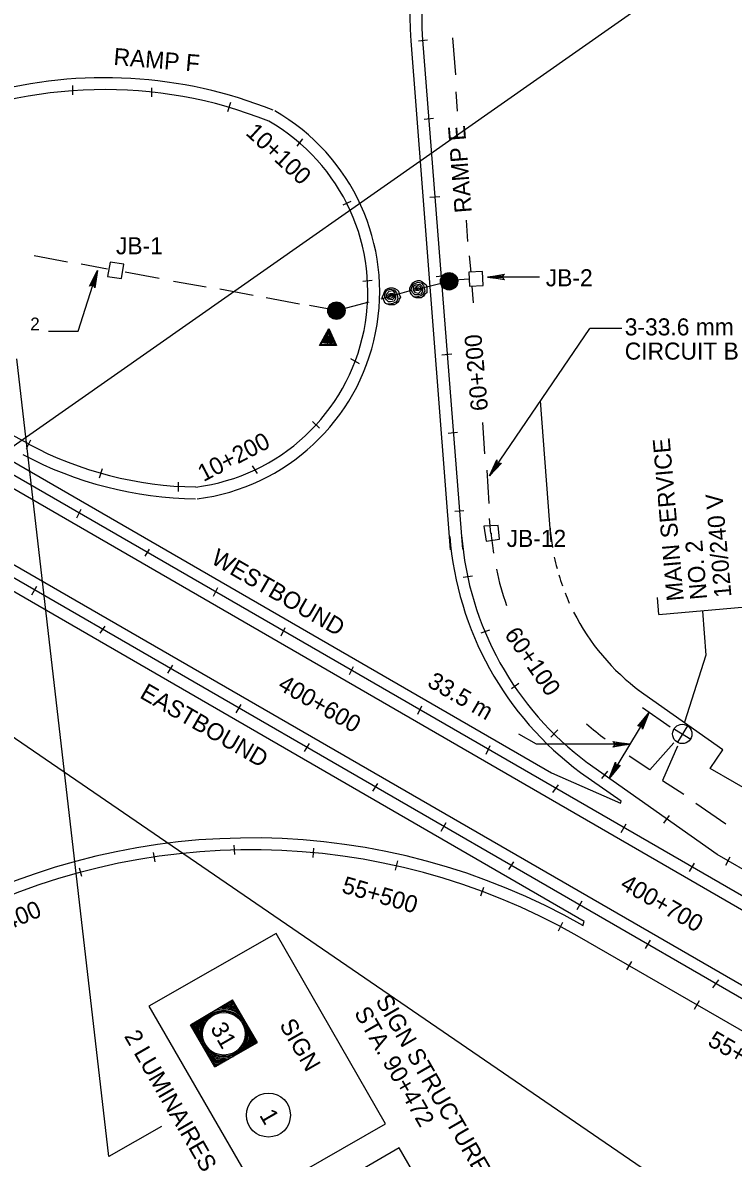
# Model space of a CAD drawing. Extents: x 36 to 2622, y -5330 to 219.
# Drawn here: x 2175.5 to 2300.3, y -4537.5 to -4338.2 of the extents above; entities that cross this region are included whole.
import ezdxf

# ---------------------------------------------------------------- set-up
doc = ezdxf.new("R2010")
doc.units = 0
doc.layers.add('2', color=7, linetype='Continuous')
doc.layers.add('3', color=7, linetype='Continuous')

# ---------------------------------------------------------------- blocks, each defined once
blk = doc.blocks.new('RARROW')
at = {"layer": '3'}
blk.add_lwpolyline([(-2.2695, 0.285), (-2.184875, 0.12075), (0, 0), (-2.2695, 0.285), (-2.38575, 0.384625), (0, 0), (-2.183125, -0.108), (-2.262875, -0.2705), (0, 0), (-2.38575, -0.379125), (-2.262875, -0.2705)], dxfattribs=at)

msp = doc.modelspace()

# ---------------------------------------------------------------- linework, layer by layer
at = {"layer": '2'}
for p, q in [((2538.01, -4157.41), (1748.46, -4710.54)), ((1732.85, -4161.87), (2538.01, -4712.77)), ((2250.61, -4430.7), (2243.73, -4341.33)), ((2244.98, -4341.33), (2246.61, -4341.2)), ((2245.73, -4341.2), (2252.73, -4430.58)), ((2250.98, -4340.83), (2251.48, -4347.33)), ((2184.23, -4349.2), (2184.23, -4350.83)), ((2198.11, -4349.58), (2198.11, -4351.2)), ((2251.86, -4353.7), (2251.61, -4350.33)), ((2211.98, -4352.2), (2211.48, -4353.83)), ((2245.98, -4355.08), (2247.61, -4354.95)), ((2224.61, -4358.58), (2223.61, -4359.83)), ((2246.98, -4368.83), (2248.73, -4368.7)), ((2233.11, -4369.58), (2231.73, -4370.2)), ((2253.36, -4372.83), (2253.61, -4376.58)), ((2183.36, -4380.2), (2177.48, -4379.08)), ((2254.23, -4381.95), (2253.98, -4379.08)), ((2176.48, -4412.08), (2115.98, -4379.95)), ((2190.36, -4381.45), (2185.73, -4380.58)), ((2381.86, -4540.2), (2110.36, -4383.33)), ((2185.22, -4392.32), (2188.61, -4381.7)), ((2199.48, -4383.08), (2193.48, -4381.95)), ((2236.86, -4383.45), (2235.23, -4383.58)), ((2248.11, -4382.7), (2249.73, -4382.58)), ((2253.86, -4383.2), (2250.48, -4383.45)), ((2266.23, -4382.83), (2257.11, -4382.83)), ((2382.98, -4538.33), (2117.11, -4384.83)), ((2207.73, -4384.58), (2201.98, -4383.58)), ((2215.98, -4386.08), (2210.11, -4384.95)), ((2243.73, -4385.2), (2238.36, -4386.7)), ((2250.36, -4383.58), (2245.48, -4384.83)), ((2254.36, -4384.45), (2254.61, -4387.33)), ((2224.11, -4387.58), (2218.23, -4386.45)), ((2230.61, -4388.7), (2236.36, -4387.2)), ((2230.61, -4388.7), (2225.86, -4387.83)), ((2375.11, -4551.83), (2096.98, -4391.2)), ((2376.11, -4550.08), (2099.11, -4390.2)), ((2180.03, -4392.32), (2185.22, -4392.32)), ((2227.61, -4394.83), (2229.23, -4391.83)), ((2227.73, -4394.7), (2229.23, -4391.95)), ((2227.86, -4394.58), (2229.23, -4392.2)), ((2228.11, -4394.33), (2229.23, -4392.45)), ((2228.36, -4394.33), (2229.11, -4392.7)), ((2228.48, -4394.2), (2229.11, -4393.08)), ((2228.73, -4394.08), (2229.11, -4393.2)), ((2229.11, -4392.7), (2229.98, -4394.33)), ((2229.11, -4393.08), (2229.86, -4394.2)), ((2229.11, -4393.2), (2229.61, -4394.08)), ((2229.23, -4391.83), (2230.61, -4394.83)), ((2229.23, -4391.95), (2230.48, -4394.83)), ((2229.23, -4392.2), (2230.36, -4394.7)), ((2229.23, -4392.45), (2230.23, -4394.58)), ((2257.48, -4417.7), (2275.11, -4391.83)), ((2280.73, -4391.83), (2275.11, -4391.83)), ((2230.61, -4394.83), (2227.61, -4394.83)), ((2230.48, -4394.83), (2227.73, -4394.7)), ((2230.36, -4394.7), (2227.86, -4394.58)), ((2230.23, -4394.58), (2228.11, -4394.33)), ((2229.98, -4394.33), (2228.36, -4394.33)), ((2229.86, -4394.2), (2228.48, -4394.2)), ((2229.61, -4394.08), (2228.73, -4394.08)), ((2228.86, -4393.95), (2229.11, -4393.45)), ((2229.36, -4394.08), (2228.86, -4393.95)), ((2228.98, -4393.95), (2229.11, -4393.7)), ((2229.23, -4393.95), (2228.98, -4393.95)), ((2229.11, -4393.45), (2229.36, -4394.08)), ((2229.11, -4393.7), (2229.23, -4393.95)), ((2141.73, -4396.7), (2268.36, -4469.83)), ((2190.61, -4537.2), (2174.48, -4397.2)), ((2234.61, -4398.08), (2233.11, -4397.2)), ((2249.11, -4396.45), (2250.86, -4396.33)), ((2266.36, -4404.58), (2268.23, -4429.33)), ((2227.61, -4409.33), (2226.36, -4408.2)), ((2256.23, -4408.33), (2256.61, -4413.83)), ((2250.23, -4410.2), (2251.86, -4410.08)), ((2176.86, -4411.45), (2176.11, -4412.95)), ((2188.98, -4418.08), (2189.48, -4416.45)), ((2216.73, -4417.33), (2215.86, -4415.95)), ((2256.98, -4416.7), (2257.36, -4422.58)), ((2202.86, -4420.45), (2202.86, -4418.83)), ((2184.98, -4425.08), (2185.73, -4423.58)), ((2251.36, -4423.95), (2252.98, -4423.83)), ((2257.73, -4427.83), (2257.48, -4425.2)), ((2274.11, -4495.95), (2152.11, -4425.45)), ((2196.98, -4431.83), (2197.73, -4430.58)), ((2177.11, -4438.58), (2177.98, -4437.08)), ((2254.48, -4435.33), (2252.86, -4435.58)), ((2208.98, -4438.83), (2209.73, -4437.33)), ((2287.23, -4442.08), (2286.98, -4439.08)), ((2287.23, -4442.08), (2302.48, -4440.7)), ((2294.86, -4441.45), (2295.48, -4449.2)), ((2189.11, -4445.33), (2189.98, -4444.08)), ((2220.86, -4445.83), (2221.61, -4444.33)), ((2257.48, -4444.83), (2255.98, -4445.33)), ((2295.48, -4449.2), (2291.73, -4460.95)), ((2200.98, -4452.33), (2201.86, -4450.95)), ((2232.86, -4452.58), (2233.61, -4451.2)), ((2262.61, -4454.2), (2261.36, -4455.08)), ((2298.48, -4465.83), (2283.61, -4455.33)), ((2212.98, -4459.33), (2213.86, -4457.83)), ((2244.86, -4459.58), (2245.61, -4458.08)), ((2289.23, -4461.83), (2284.36, -4458.45)), ((2285.48, -4459.33), (2278.48, -4470.83)), ((2265.73, -4464.83), (2262.61, -4463.08)), ((2269.48, -4462.33), (2268.23, -4463.58)), ((2289.98, -4462.2), (2292.86, -4463.95)), ((2292.23, -4461.58), (2290.48, -4464.45)), ((2224.98, -4466.08), (2225.86, -4464.7)), ((2256.86, -4466.58), (2257.61, -4465.08)), ((2282.13, -4464.83), (2265.73, -4464.83)), ((2289.86, -4464.58), (2285.61, -4469.33)), ((2290.48, -4465.2), (2287.86, -4471.2)), ((2285.61, -4469.33), (2281.98, -4466.95)), ((2296.23, -4469.08), (2298.48, -4465.83)), ((2297.48, -4484.2), (2274.61, -4468.08)), ((2344.23, -4496.83), (2296.23, -4469.08)), ((2268.36, -4469.83), (2280.48, -4475.2)), ((2280.61, -4474.83), (2273.48, -4469.83)), ((2277.23, -4470.83), (2278.23, -4469.58)), ((2236.98, -4473.08), (2237.86, -4471.7)), ((2268.61, -4473.33), (2269.61, -4471.95)), ((2287.86, -4471.2), (2291.61, -4473.58)), ((2280.48, -4475.2), (2280.61, -4474.83)), ((2293.73, -4475.2), (2298.98, -4478.83)), ((2248.98, -4480.08), (2249.86, -4478.58)), ((2280.61, -4480.33), (2281.48, -4478.83)), ((2288.11, -4478.7), (2289.11, -4477.33)), ((2212.73, -4484.2), (2212.61, -4482.58)), ((2226.48, -4484.7), (2226.61, -4483.08)), ((2198.73, -4485.45), (2198.48, -4483.83)), ((2384.98, -4534.7), (2297.48, -4484.2)), ((2298.98, -4486.08), (2299.73, -4484.58)), ((2185.86, -4488.08), (2185.48, -4486.58)), ((2240.98, -4486.95), (2241.36, -4485.33)), ((2260.86, -4486.83), (2261.73, -4485.45)), ((2292.61, -4487.2), (2293.48, -4485.7)), ((2255.98, -4491.45), (2256.48, -4489.95)), ((2272.86, -4493.83), (2273.73, -4492.33)), ((2269.61, -4497.58), (2270.36, -4496.08)), ((2273.86, -4496.7), (2274.11, -4495.95)), ((2372.73, -4556.08), (2272.86, -4498.45)), ((2284.86, -4500.7), (2285.73, -4499.2)), ((2281.61, -4504.45), (2282.48, -4502.95)), ((2296.73, -4507.58), (2297.73, -4506.2)), ((2293.48, -4511.33), (2294.36, -4509.83)), ((2199.86, -4531.95), (2190.61, -4537.2))]:
    msp.add_line(p, q, dxfattribs=at)
for points in [[(2192.86, -4383.08), (2193.23, -4380.58), (2190.86, -4380.2), (2190.36, -4382.7)], [(2253.98, -4384.45), (2256.36, -4384.33), (2256.23, -4381.83), (2253.86, -4381.95)], [(2256.86, -4429.2), (2259.23, -4428.83), (2258.98, -4426.45), (2256.48, -4426.58)], [(2197.61, -4510.83), (2216.98, -4544.2), (2239.23, -4531.45), (2219.98, -4498.08)], [(2219.48, -4548.58), (2238.61, -4582.08), (2260.98, -4569.2), (2241.61, -4535.7)]]:
    msp.add_lwpolyline(points, close=True, dxfattribs=at)
for points in [[(2244.98, -4384.95), (2244.61, -4384.95), (2244.61, -4384.7), (2244.98, -4384.7), (2245.23, -4384.83), (2245.23, -4385.08), (2244.98, -4385.2), (2244.48, -4385.2), (2244.36, -4384.83), (2244.48, -4384.58), (2244.86, -4384.33), (2245.23, -4384.45), (2245.48, -4384.83), (2245.48, -4385.2), (2244.98, -4385.7), (2244.48, -4385.58), (2244.11, -4385.08), (2244.11, -4384.45), (2244.48, -4384.2), (2245.23, -4384.08), (2245.61, -4384.45), (2245.73, -4384.83), (2245.73, -4385.33), (2245.48, -4385.83), (2244.98, -4385.95), (2244.36, -4385.95), (2243.98, -4385.58), (2243.73, -4385.08), (2243.86, -4384.58), (2244.11, -4384.08), (2244.86, -4383.7), (2245.48, -4383.83), (2245.86, -4384.33), (2245.98, -4384.7), (2246.11, -4385.33), (2245.73, -4385.95), (2245.23, -4386.2), (2244.61, -4386.33), (2244.23, -4386.33), (2243.86, -4385.95), (2243.61, -4385.58), (2243.48, -4385.08), (2243.48, -4384.7), (2243.73, -4384.33), (2243.98, -4383.83), (2244.36, -4383.58), (2244.86, -4383.45), (2245.23, -4383.45), (2245.61, -4383.58), (2245.86, -4383.83), (2246.36, -4384.2), (2246.48, -4384.58), (2246.48, -4385.08), (2246.48, -4385.58), (2246.11, -4385.83), (2245.86, -4386.2), (2245.48, -4386.45), (2245.11, -4386.45), (2244.61, -4386.45), (2244.23, -4386.33), (2243.98, -4386.2)], [(2240.11, -4386.2), (2239.86, -4386.2), (2239.98, -4385.95), (2240.36, -4385.95), (2240.48, -4386.08), (2240.48, -4386.33), (2240.11, -4386.58), (2239.73, -4386.45), (2239.61, -4386.08), (2239.73, -4385.83), (2240.11, -4385.7), (2240.48, -4385.7), (2240.73, -4386.08), (2240.73, -4386.45), (2240.36, -4386.83), (2239.73, -4386.7), (2239.36, -4386.33), (2239.36, -4385.83), (2239.86, -4385.33), (2240.48, -4385.2), (2240.86, -4385.7), (2240.98, -4386.08), (2240.98, -4386.58), (2240.73, -4387.08), (2240.11, -4387.2), (2239.73, -4387.2), (2239.36, -4386.83), (2239.11, -4386.33), (2239.11, -4385.83), (2239.36, -4385.2), (2239.98, -4384.95), (2240.73, -4385.08), (2241.11, -4385.58), (2241.23, -4385.95), (2241.36, -4386.58), (2241.11, -4387.2), (2240.48, -4387.45), (2239.86, -4387.58), (2239.48, -4387.58), (2239.11, -4387.33), (2238.86, -4386.7), (2238.61, -4386.33), (2238.86, -4385.95), (2238.98, -4385.58), (2239.23, -4385.08), (2239.61, -4384.83), (2239.98, -4384.7), (2240.48, -4384.7), (2240.86, -4384.83), (2241.23, -4385.08), (2241.48, -4385.33), (2241.61, -4385.83), (2241.86, -4386.33), (2241.61, -4386.7), (2241.48, -4387.2), (2241.11, -4387.45), (2240.73, -4387.7), (2240.36, -4387.7), (2239.86, -4387.7), (2239.61, -4387.58), (2239.23, -4387.45)], [(2204.98, -4514.08), (2212.36, -4509.7)], [(2216.73, -4517.2), (2212.36, -4509.7)], [(2209.23, -4521.45), (2204.98, -4514.08)], [(2209.23, -4521.45), (2216.73, -4517.2)]]:
    msp.add_lwpolyline(points, dxfattribs=at)
for centre, radius in [((2250.37, -4383.57), 1.53), ((2250.37, -4383.57), 1.42), ((2250.37, -4383.57), 1.31), ((2250.37, -4383.57), 1.21), ((2250.37, -4383.57), 1.1), ((2250.37, -4383.57), 0.988), ((2250.37, -4383.57), 0.88), ((2250.37, -4383.57), 0.771), ((2250.37, -4383.57), 0.662), ((2250.37, -4383.57), 0.553), ((2250.37, -4383.57), 0.444), ((2250.37, -4383.57), 0.335), ((2250.37, -4383.57), 0.226), ((2250.37, -4383.57), 0.118), ((2230.59, -4388.72), 1.53), ((2230.59, -4388.72), 1.42), ((2230.59, -4388.72), 1.31), ((2230.59, -4388.72), 1.21), ((2230.59, -4388.72), 1.1), ((2230.59, -4388.72), 0.988), ((2230.59, -4388.72), 0.88), ((2230.59, -4388.72), 0.771), ((2230.59, -4388.72), 0.662), ((2230.59, -4388.72), 0.553), ((2230.59, -4388.72), 0.444), ((2230.59, -4388.72), 0.335), ((2230.59, -4388.72), 0.226), ((2230.59, -4388.72), 0.118), ((2291.33, -4463.03), 1.7), ((2210.81, -4515.65), 4.13), ((2210.81, -4515.65), 3.95), ((2210.81, -4515.65), 3.74), ((2218.65, -4529.94), 3.86)]:
    msp.add_circle(centre, radius, dxfattribs=at)
for centre, radius, start, end in [((2299.5, -4337), 56.03, 117.5941, 184.4997), ((2299.5, -4337), 53.94, 117.5941, 184.4997), ((2189.88, -4427.46), 79.63, 68.1807, 105.2322), ((2189.88, -4427.46), 77.55, 68.1807, 114.519), ((2201.58, -4385.43), 34.52, 277.1666, 60.2478), ((2201.58, -4385.43), 36.6, 277.1666, 60.2478), ((2206.75, -4355.16), 64.52, 242.0007, 269.2348), ((2206.75, -4355.16), 66.6, 242.0007, 269.2348), ((2307.6, -4423.76), 39.61, 184.5928, 189.5111), ((2307.6, -4423.76), 57.3, 184.5916, 233.4476), ((2307.6, -4423.76), 55.21, 184.5916, 233.3995), ((2307.6, -4423.76), 50.01, 184.5916, 188.6652), ((2307.6, -4423.76), 39.61, 191.9665, 194.9428), ((2307.6, -4423.76), 50.01, 191.9521, 199.5366), ((2307.6, -4423.76), 39.61, 196.675, 199.5883), ((2307.6, -4423.76), 39.61, 201.4586, 204.2855), ((2307.6, -4423.76), 39.61, 206.8227, 233.4003), ((2307.6, -4423.76), 50.01, 228.5971, 233.3995), ((2215.68, -4599.27), 117.99, 60.4381, 117.8815), ((2215.68, -4599.27), 115.91, 60.4381, 117.8802), ((2210.81, -4515.65), 4.73, 54.8374, 95.1626), ((2210.81, -4515.65), 4.89, 58.4912, 91.5088), ((2210.81, -4515.65), 5.06, 62.0046, 87.9954), ((2210.81, -4515.65), 5.26, 65.2513, 84.7486), ((2210.81, -4515.65), 5.45, 67.9632, 82.0368), ((2210.81, -4515.65), 5.62, 70.1586, 79.8414), ((2210.81, -4515.65), 5.8, 72.2128, 77.7872), ((2210.81, -4515.65), 4.73, 144.8374, 185.031), ((2210.81, -4515.65), 4.53, 138.594, 191.2253), ((2210.81, -4515.65), 4.32, 126.379, 203.0962), ((2210.81, -4515.65), 4.32, 36.379, 113.621), ((2210.81, -4515.65), 4.53, 48.594, 101.406), ((2210.81, -4515.65), 5.8, 162.2128, 167.7199), ((2210.81, -4515.65), 5.62, 160.1586, 169.769), ((2210.81, -4515.65), 5.45, 157.9632, 171.9586), ((2210.81, -4515.65), 5.26, 155.2513, 174.6623), ((2210.81, -4515.65), 5.06, 152.0046, 177.8978), ((2210.81, -4515.65), 4.89, 148.4912, 181.3964), ((2210.81, -4515.65), 4.32, 306.9038, 23.621), ((2210.81, -4515.65), 4.53, 318.7747, 11.406), ((2210.81, -4515.65), 4.73, 324.969, 5.1626), ((2210.81, -4515.65), 4.89, 328.6036, 1.5088), ((2210.81, -4515.65), 5.06, 332.1022, 357.9954), ((2210.81, -4515.65), 5.26, 335.3377, 354.7486), ((2210.81, -4515.65), 5.45, 338.0414, 352.0368), ((2210.81, -4515.65), 5.62, 340.231, 349.8414), ((2210.81, -4515.65), 5.8, 342.2801, 347.7872), ((2210.81, -4515.65), 4.32, 216.9038, 293.0962), ((2210.81, -4515.65), 4.53, 228.7747, 281.2253), ((2210.81, -4515.65), 4.73, 234.969, 275.031), ((2210.81, -4515.65), 4.89, 238.6036, 271.3964), ((2210.81, -4515.65), 5.06, 242.1022, 267.8978), ((2210.81, -4515.65), 5.26, 245.3377, 264.6623), ((2210.81, -4515.65), 5.45, 248.0414, 261.9586), ((2210.81, -4515.65), 5.62, 250.231, 259.769), ((2210.81, -4515.65), 5.8, 252.2801, 257.7199)]:
    msp.add_arc(centre, radius, start, end, dxfattribs=at)

# ---------------------------------------------------------------- block references
for p, xscale, yscale, rotation in [((2188.61, -4381.7), 1.2574347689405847, 1.3092961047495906, 72.29710976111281), ((2257.11, -4382.83), 1.2574347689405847, 1.3092961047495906, 180), ((2257.48, -4417.7), 1.2574347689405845, 1.3092961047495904, -124.10659777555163), ((2285.48, -4459.33), 1.2574347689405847, 1.3092961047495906, 59.139364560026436), ((2278.48, -4470.83), 1.257434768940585, 1.3092961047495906, -120.78069932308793)]:
    msp.add_blockref('RARROW', p, dxfattribs=dict(at, xscale=xscale, yscale=yscale, rotation=rotation))
at = {"layer": '2', "xscale": 1.2574347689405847, "yscale": 1.3092961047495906}
msp.add_blockref('RARROW', (2282.13, -4464.83), dxfattribs=at)

# ---------------------------------------------------------------- texts
at = {"layer": '2'}
for s, height, rotation, p in [('RAMP F', 2.996, 355.2917, (2191.36, -4345.58)), ('10+100', 3, 317.3246, (2214.48, -4357.7)), ('RAMP E', 2.996, 94.4995, (2254.36, -4371.45)), ('2', 2.25, 0.0055, (2176.8, -4392.19)), ('3-33.6 mm', 2.996, 360, (2281.23, -4393.07)), ('60+200', 3, 95.0793, (2257.23, -4406.2)), ('CIRCUIT B', 2.996, 360, (2281.23, -4397.32)), ('10+200', 3, 27.5003, (2207.23, -4418.83)), ('MAIN SERVICE', 2.9955, 95, (2291.61, -4439.58)), ('120/240 V', 2.996, 95, (2299.98, -4438.95)), ('NO. 2', 2.996, 95, (2295.73, -4439.33)), ('WESTBOUND', 2.996, 330.0015, (2208.36, -4432.95)), ('60+100', 3, 304.8235, (2259.98, -4445.58)), ('400+600', 3, 330, (2220.11, -4455.08)), ('33.5 m', 3, 330, (2246.36, -4454.58)), ('EASTBOUND', 2.996, 330.0015, (2195.86, -4456.58)), ('55+500', 3, 343.95, (2231.36, -4490.83)), ('400+700', 3, 330, (2280.23, -4490.08)), ('55+400', 3, 22.964, (2166.61, -4500.2)), ('SIGN STRUCTURE NO.7', 2.9955, 300, (2237.36, -4509.83)), ('STA. 90+472', 2.9955, 300, (2233.61, -4511.95)), ('SIGN', 2.996, 300, (2220.48, -4514.08)), ('2 LUMINAIRES', 2.9955, 300, (2193.23, -4516.08)), ('31', 2.996, 300, (2208.36, -4514.7)), ('55+600', 3, 329.9959, (2295.61, -4517.58)), ('1', 3, 300, (2216.98, -4529.95))]:
    msp.add_text(s, height=height, rotation=rotation, dxfattribs=at).set_placement(p)
for s, p in [('JB-1', (2191.86, -4378.83)), ('JB-2', (2267.36, -4384.45)), ('JB-12', (2260.48, -4430.2))]:
    msp.add_text(s, height=2.996, dxfattribs=at).set_placement(p)

doc.saveas('drawing.dxf')
